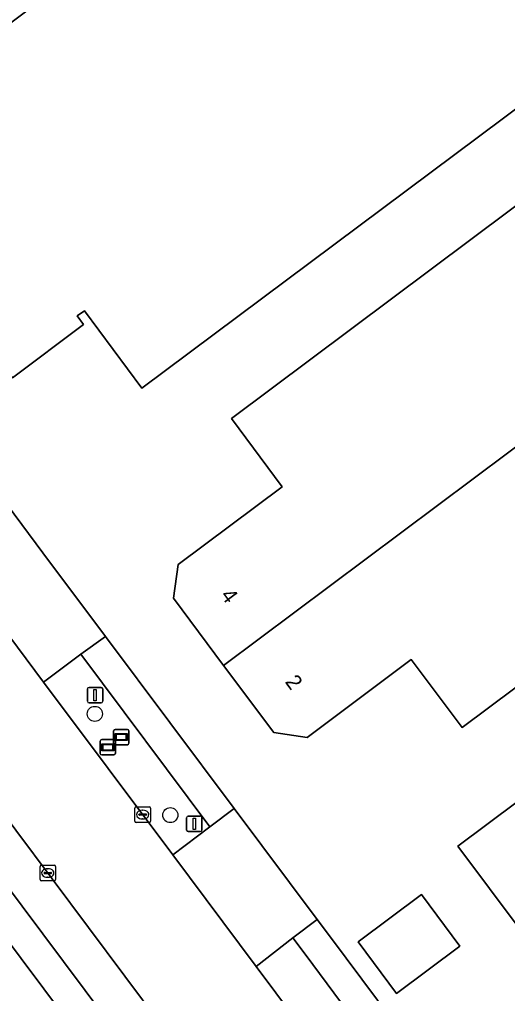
# Model space of a CAD drawing. Extents: x 156702 to 158052, y 387630 to 388992.
# Drawn here: x 157762.9 to 157794.6, y 388521.6 to 388584.8 of the extents above; entities that cross this region are included whole.
import ezdxf

# ---------------------------------------------------------------- set-up
doc = ezdxf.new("R2010")
doc.units = 0
for name, color, linetype in [('IMGEO_Berm_groen', 7, 'Continuous'), ('IMGEO_Boom', 7, 'Continuous'), ('IMGEO_Erf', 7, 'Continuous'), ('IMGEO_Informatiebord', 7, 'Continuous'), ('IMGEO_Kolk', 7, 'Continuous'), ('IMGEO_Pand', 7, 'Continuous'), ('IMGEO_Pand_nummerreeks', 7, 'Continuous'), ('IMGEO_Parkeervlak_open', 7, 'Continuous'), ('IMGEO_Rijbaan_lokaal_gesloten', 7, 'Continuous'), ('IMGEO_Verkeersbordpaal', 7, 'Continuous'), ('IMGEO_Voetpad_open', 7, 'Continuous')]:
    doc.layers.add(name, color=color, linetype=linetype)

msp = doc.modelspace()

# ---------------------------------------------------------------- linework, layer by layer
at = {"layer": 'IMGEO_Berm_groen'}
for points in [[(157766.867, 388543.606), (157764.445, 388541.799), (157772.827, 388530.595), (157775.238, 388532.42)], [(157781.487, 388524.062), (157780.627, 388525.218), (157778.233, 388523.368), (157787.118, 388511.491), (157789.539, 388513.228)]]:
    msp.add_lwpolyline(points, close=True, dxfattribs=at)
at = {"layer": 'IMGEO_Boom'}
for centre in [(157767.774, 388539.744), (157772.671, 388533.178)]:
    msp.add_circle(centre, 0.489, dxfattribs=at)
at = {"layer": 'IMGEO_Erf'}
for points in [[(157680.574, 388662.334), (157682.743, 388659.448), (157709.701, 388623.366), (157713.197, 388618.671), (157726.014, 388601.557), (157732.023, 388593.501), (157733.413, 388591.636), (157742.964, 388578.821), (157747.063, 388573.387), (157747.131, 388573.296), (157758.423, 388558.206), (157764.403, 388550.183), (157768.457, 388544.772), (157776.821, 388533.611), (157782.202, 388526.417), (157783.072, 388525.255), (157791.129, 388514.451), (157796.618, 388507.108), (157801.963, 388500), (157804.872, 388496.027), (157807.002, 388493.227), (157808.72, 388490.73)], [(157788.87, 388469.419), (157788.977, 388469.333), (157795.516, 388475.573), (157796.754, 388477.777), (157795.152, 388480.693), (157794.961, 388480.951), (157786.146, 388492.867), (157782.722, 388497.479), (157780.836, 388500), (157742.183, 388551.677), (157734.591, 388561.818), (157727.725, 388570.997), (157720.519, 388580.603), (157669.545, 388648.866)]]:
    msp.add_lwpolyline(points, dxfattribs=at)
for points in [[(157795.49, 388609.351), (157800.933, 388602.076), (157809.912, 388590.06), (157770.834, 388560.859), (157767.103, 388565.883), (157766.618, 388565.55), (157767.037, 388564.99), (157762.428, 388561.536), (157758.085, 388567.345), (157758.389, 388567.572), (157758.103, 388567.958), (157757.203, 388567.285), (157755.975, 388568.927), (157756.875, 388569.597), (157756.586, 388569.987), (157756.282, 388569.759), (157751.946, 388575.556), (157756.546, 388578.995), (157756.971, 388578.426), (157757.429, 388578.783), (157756.406, 388580.153)], [(157810.284, 388584.036), (157817.772, 388574.014), (157825.259, 388563.992), (157791.614, 388538.852), (157788.3, 388543.26), (157781.551, 388538.207), (157779.382, 388538.534), (157776.132, 388542.884), (157772.876, 388547.242), (157773.177, 388549.426), (157779.926, 388554.478), (157776.634, 388558.897)], [(157827.776, 388558.382), (157844.257, 388536.356), (157823.506, 388520.914), (157824.174, 388520.021), (157824.869, 388520.528), (157829.311, 388514.601), (157812.889, 388502.304), (157808.45, 388508.262), (157809.15, 388508.808), (157808.513, 388509.637), (157807.828, 388509.101), (157791.323, 388531.165)], [(157788.981, 388528.025), (157791.467, 388524.674), (157787.347, 388521.617), (157784.861, 388524.968)]]:
    msp.add_lwpolyline(points, close=True, dxfattribs=at)
at = {"layer": 'IMGEO_Informatiebord'}
for p, q in [((157768.994, 388537.841), (157768.994, 388538.641)), ((157768.994, 388538.641), (157768.994, 388537.841)), ((157769.094, 388538.741), (157769.884, 388538.741)), ((157769.884, 388538.741), (157769.094, 388538.741)), ((157769.984, 388538.641), (157769.984, 388537.841)), ((157769.984, 388537.841), (157769.984, 388538.641)), ((157768.121, 388537.177), (157768.121, 388537.977)), ((157768.121, 388537.977), (157768.121, 388537.177)), ((157768.221, 388538.077), (157769.011, 388538.077)), ((157769.011, 388538.077), (157768.221, 388538.077)), ((157769.884, 388537.741), (157769.094, 388537.741)), ((157769.094, 388537.741), (157769.884, 388537.741)), ((157769.111, 388537.977), (157769.111, 388537.177)), ((157769.111, 388537.177), (157769.111, 388537.977)), ((157769.011, 388537.077), (157768.221, 388537.077)), ((157768.221, 388537.077), (157769.011, 388537.077))]:
    msp.add_line(p, q, dxfattribs=at)
for points in [[(157769.095, 388538.473), (157769.883, 388538.473), (157769.883, 388538.009), (157769.095, 388538.009), (157769.095, 388538.473)], [(157769.16, 388538.408), (157769.16, 388538.074), (157769.818, 388538.074), (157769.818, 388538.408), (157769.16, 388538.408)], [(157768.222, 388537.809), (157769.01, 388537.809), (157769.01, 388537.345), (157768.222, 388537.345), (157768.222, 388537.809)], [(157768.287, 388537.744), (157768.287, 388537.41), (157768.945, 388537.41), (157768.945, 388537.744), (157768.287, 388537.744)]]:
    msp.add_lwpolyline(points, dxfattribs=at)
for centre, start, end in [((157769.094, 388538.641), 90, 180), ((157769.094, 388538.641), 90, 180), ((157769.884, 388538.641), 0, 90), ((157769.884, 388538.641), 360, 90), ((157768.221, 388537.977), 90, 180), ((157768.221, 388537.977), 90, 180), ((157769.094, 388537.841), 180, 270), ((157769.094, 388537.841), 180, 270), ((157769.011, 388537.977), 0, 90), ((157769.011, 388537.977), 360, 90), ((157769.884, 388537.841), 270, 0), ((157769.884, 388537.841), 270, 0), ((157768.221, 388537.177), 180, 270), ((157768.221, 388537.177), 180, 270), ((157769.011, 388537.177), 270, 0), ((157769.011, 388537.177), 270, 0)]:
    msp.add_arc(centre, 0.1, start, end, dxfattribs=at)
at = {"layer": 'IMGEO_Kolk'}
for p, q in [((157770.379, 388532.783), (157770.379, 388533.635)), ((157770.454, 388533.709), (157771.306, 388533.709)), ((157770.638, 388533.203), (157770.638, 388533.215)), ((157771.076, 388533.166), (157770.678, 388533.166)), ((157770.681, 388533.252), (157771.079, 388533.252)), ((157770.867, 388533.489), (157770.892, 388533.489)), ((157771.122, 388533.215), (157771.122, 388533.203)), ((157771.38, 388533.635), (157771.38, 388532.783)), ((157771.306, 388532.709), (157770.454, 388532.709)), ((157770.89, 388532.929), (157770.865, 388532.929)), ((157764.22, 388528.997), (157764.22, 388529.849)), ((157764.295, 388529.923), (157765.147, 388529.923)), ((157764.479, 388529.417), (157764.479, 388529.429)), ((157764.917, 388529.38), (157764.519, 388529.38)), ((157764.522, 388529.466), (157764.92, 388529.466)), ((157764.708, 388529.703), (157764.733, 388529.703)), ((157764.963, 388529.429), (157764.963, 388529.417)), ((157765.221, 388529.849), (157765.221, 388528.997)), ((157765.147, 388528.923), (157764.295, 388528.923)), ((157764.731, 388529.143), (157764.706, 388529.143))]:
    msp.add_line(p, q, dxfattribs=at)
for points in [[(157770.379, 388532.783), (157770.379, 388533.635)], [(157770.454, 388533.709), (157771.306, 388533.709)], [(157771.38, 388533.635), (157771.38, 388532.783)], [(157771.306, 388532.709), (157770.454, 388532.709)], [(157764.22, 388528.997), (157764.22, 388529.849)], [(157764.295, 388529.923), (157765.147, 388529.923)], [(157765.221, 388529.849), (157765.221, 388528.997)], [(157765.147, 388528.923), (157764.295, 388528.923)]]:
    msp.add_lwpolyline(points, dxfattribs=at)
for centre, radius, start, end in [((157770.456, 388533.633), 0.0765, 91.55205, 178.44795), ((157770.456, 388533.633), 0.0765, 91.55205, 178.44795), ((157770.678, 388533.212), 0.0403, 85.87752, 175.75265), ((157770.675, 388533.202), 0.0366, 178.93798, 274.71019), ((157771.079, 388533.209), 0.043, 264.86636, 352.45326), ((157771.083, 388533.214), 0.0386, 1.73085, 96.63898), ((157771.304, 388533.633), 0.0765, 1.55205, 88.44795), ((157771.304, 388533.633), 0.0765, 1.55205, 88.44795), ((157770.456, 388532.785), 0.0765, 181.55205, 268.44795), ((157770.456, 388532.785), 0.0765, 181.55205, 268.44795), ((157771.304, 388532.785), 0.0765, 271.55205, 358.44795), ((157771.304, 388532.785), 0.0765, 271.55205, 358.44795), ((157764.297, 388529.847), 0.0765, 91.55205, 178.44795), ((157764.297, 388529.847), 0.0765, 91.55205, 178.44795), ((157764.519, 388529.426), 0.0403, 85.87752, 175.75265), ((157764.516, 388529.416), 0.0366, 178.93798, 274.71019), ((157764.92, 388529.423), 0.043, 264.86636, 352.45326), ((157764.924, 388529.428), 0.0386, 1.73085, 96.63898), ((157765.145, 388529.847), 0.0765, 1.55205, 88.44795), ((157765.145, 388529.847), 0.0765, 1.55205, 88.44795), ((157764.297, 388528.999), 0.0765, 181.55205, 268.44795), ((157764.297, 388528.999), 0.0765, 181.55205, 268.44795), ((157765.145, 388528.999), 0.0765, 271.55205, 358.44795), ((157765.145, 388528.999), 0.0765, 271.55205, 358.44795)]:
    msp.add_arc(centre, radius, start, end, dxfattribs=at)
for centre, major_axis, ratio, start_param, end_param in [((157770.866, 388533.209), (-0.387, 0.002), 0.722429, 4.712389, 7.853982), ((157770.891, 388533.209), (-0.39, 0.002), 0.717154, 1.570796, 4.712389), ((157764.707, 388529.423), (-0.387, 0.002), 0.722429, 4.712389, 7.853982), ((157764.732, 388529.423), (-0.39, 0.002), 0.717154, 1.570796, 4.712389)]:
    msp.add_ellipse(centre, major_axis=major_axis, ratio=ratio, start_param=start_param, end_param=end_param, dxfattribs=at)
at = {"layer": 'IMGEO_Pand'}
for points in [[(157770.834, 388560.859), (157809.912, 388590.06), (157800.933, 388602.076), (157795.49, 388609.351), (157756.406, 388580.153), (157757.429, 388578.783), (157756.971, 388578.426), (157756.546, 388578.995), (157751.946, 388575.556), (157756.282, 388569.759), (157756.586, 388569.987), (157756.875, 388569.597), (157755.975, 388568.927), (157757.203, 388567.285), (157758.103, 388567.958), (157758.389, 388567.572), (157758.085, 388567.345), (157762.428, 388561.536), (157767.037, 388564.99), (157766.618, 388565.55), (157767.103, 388565.883)], [(157817.772, 388574.014), (157810.284, 388584.036), (157776.634, 388558.897), (157779.926, 388554.478), (157773.177, 388549.426), (157772.876, 388547.242), (157776.132, 388542.884)], [(157817.772, 388574.014), (157776.132, 388542.884), (157779.382, 388538.534), (157781.551, 388538.207), (157788.3, 388543.26), (157791.614, 388538.852), (157825.259, 388563.992)], [(157812.889, 388502.304), (157829.311, 388514.601), (157824.869, 388520.528), (157824.174, 388520.021), (157823.506, 388520.914), (157844.257, 388536.356), (157827.776, 388558.382), (157791.323, 388531.165), (157807.828, 388509.101), (157808.513, 388509.637), (157809.15, 388508.808), (157808.45, 388508.262)], [(157787.347, 388521.617), (157791.467, 388524.674), (157788.981, 388528.025), (157784.861, 388524.968)]]:
    msp.add_lwpolyline(points, close=True, dxfattribs=at)
at = {"layer": 'IMGEO_Parkeervlak_open'}
msp.add_lwpolyline([(157746.116, 388554.3), (157744.014, 388552.734), (157783.436, 388500), (157784.129, 388499.072), (157786.233, 388500.645)], close=True, dxfattribs=at)
at = {"layer": 'IMGEO_Rijbaan_lokaal_gesloten'}
for points in [[(157803.729, 388489.229), (157803.007, 388490.195), (157801.032, 388492.841), (157799.207, 388495.33), (157795.714, 388500), (157792.641, 388504.108), (157787.118, 388511.491), (157778.233, 388523.368), (157772.827, 388530.595), (157764.445, 388541.799), (157760.423, 388547.176), (157754.398, 388555.23), (157743.149, 388570.269), (157743.08, 388570.36), (157739.001, 388575.812), (157729.45, 388588.589), (157727.995, 388590.535), (157721.978, 388598.584), (157709.22, 388615.65)], [(157715.525, 388595.248), (157733.77, 388570.785), (157738.371, 388564.633), (157739.101, 388563.658), (157745.11, 388555.645), (157746.116, 388554.3), (157786.233, 388500.645), (157786.715, 388500), (157790.147, 388495.41), (157797.155, 388486.037)]]:
    msp.add_lwpolyline(points, dxfattribs=at)
at = {"layer": 'IMGEO_Verkeersbordpaal'}
for p, q in [((157767.299, 388540.56), (157767.299, 388541.36)), ((157767.299, 388541.36), (157767.299, 388540.56)), ((157767.399, 388541.46), (157768.189, 388541.46)), ((157768.189, 388541.46), (157767.399, 388541.46)), ((157768.289, 388541.36), (157768.289, 388540.56)), ((157768.289, 388540.56), (157768.289, 388541.36)), ((157768.189, 388540.46), (157767.399, 388540.46)), ((157767.399, 388540.46), (157768.189, 388540.46)), ((157773.727, 388532.209), (157773.727, 388533.009)), ((157773.727, 388533.009), (157773.727, 388532.209)), ((157773.827, 388533.109), (157774.617, 388533.109)), ((157774.617, 388533.109), (157773.827, 388533.109)), ((157774.717, 388533.009), (157774.717, 388532.209)), ((157774.717, 388532.209), (157774.717, 388533.009)), ((157774.617, 388532.109), (157773.827, 388532.109)), ((157773.827, 388532.109), (157774.617, 388532.109))]:
    msp.add_line(p, q, dxfattribs=at)
for points in [[(157767.719, 388541.335), (157767.869, 388541.335), (157767.869, 388540.585), (157767.719, 388540.585), (157767.719, 388541.335)], [(157774.147, 388532.984), (157774.297, 388532.984), (157774.297, 388532.234), (157774.147, 388532.234), (157774.147, 388532.984)]]:
    msp.add_lwpolyline(points, dxfattribs=at)
for centre, start, end in [((157767.399, 388541.36), 90, 180), ((157767.399, 388541.36), 90, 180), ((157768.189, 388541.36), 0, 90), ((157768.189, 388541.36), 360, 90), ((157767.399, 388540.56), 180, 270), ((157767.399, 388540.56), 180, 270), ((157768.189, 388540.56), 270, 0), ((157768.189, 388540.56), 270, 0), ((157773.827, 388533.009), 90, 180), ((157773.827, 388533.009), 90, 180), ((157774.617, 388533.009), 0, 90), ((157774.617, 388533.009), 360, 90), ((157773.827, 388532.209), 180, 270), ((157773.827, 388532.209), 180, 270), ((157774.617, 388532.209), 270, 0), ((157774.617, 388532.209), 270, 0)]:
    msp.add_arc(centre, 0.1, start, end, dxfattribs=at)
at = {"layer": 'IMGEO_Voetpad_open'}
for points in [[(157766.867, 388543.606), (157768.457, 388544.772), (157764.403, 388550.183), (157758.423, 388558.206), (157756.814, 388557.023), (157754.398, 388555.23), (157760.423, 388547.176), (157764.445, 388541.799)], [(157744.014, 388552.734), (157743.876, 388552.919), (157742.183, 388551.677), (157780.836, 388500), (157782.722, 388497.479), (157784.4, 388498.71), (157784.129, 388499.072), (157783.436, 388500)], [(157775.238, 388532.42), (157776.821, 388533.611), (157768.457, 388544.772), (157766.867, 388543.606)], [(157772.827, 388530.595), (157778.233, 388523.368), (157780.627, 388525.218), (157782.202, 388526.417), (157776.821, 388533.611), (157775.238, 388532.42)], [(157789.539, 388513.228), (157791.129, 388514.451), (157783.072, 388525.255), (157782.202, 388526.417), (157780.627, 388525.218), (157781.487, 388524.062)]]:
    msp.add_lwpolyline(points, close=True, dxfattribs=at)

# ---------------------------------------------------------------- texts
at = {"layer": 'IMGEO_Pand_nummerreeks'}
for s, p in [('4', (157775.891, 388547.417)), ('2', (157780.077, 388541.814))]:
    msp.add_text(s, height=1, rotation=306.76448, dxfattribs=at).set_placement(p)

doc.saveas('drawing.dxf')
